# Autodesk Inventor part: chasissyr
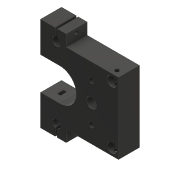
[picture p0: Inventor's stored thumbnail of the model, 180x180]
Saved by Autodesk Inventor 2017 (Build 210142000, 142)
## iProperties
Created: 2018-08
Part Number: chasissyr
Material: Plastic, Opaque Black
Document SubType Name: Modeling
Designer: JK
Density: 0.952 g/cm^3
Appearance: Smooth - Black
Author: JK
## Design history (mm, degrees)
sketch "Sketch1"
  geometry: L1 (15, 45)-(-15, 45); L2 (-15, 45)-(-15, -45); L3 (-15, -45)-(15, -45); L4 (15, -45)-(15, 45); L5 (15, 45)-(-15, -45); L6 (-15, 45)-(15, -45); L7 (-15, -45)-(-48.5, -45); L8 (-48.5, -45)-(-48.5, 45); L9 (-48.5, 45)-(-15, 45); L10 (-15, 45)-(-15, -45); C1 r 4.15 at (0, 34); C2 r 4.15 at (0, -34); 3 further points
  constraints: 20 end point, 4 parallel, 2 centre point, 2 horizontal, 2 midpoint, 2 perpendicular, 2 vertical alignment, 1 coincident, 1 equal radius
  dimensions: "d0" = 8.3 diameter of C1; "d4" = 68 distance of C2.centre C1.centre; "d5" = 34 distance of point (0, 0) C1.centre; "d6" = 90 distance of L3.end L1.start; "d7" = 30 distance of L1.start L1.end; "d14" = 33.5 distance of L8.end L9.end
extrude "Extrusion1" new body sketch "Sketch1" distance "d2" = 20; taper "d3" = 0 deg
sketch "Sketch2"
  geometry: L1 (-15, 45)-(-15, -45) reference; L2 (48.5, -45)-(48.5, 45) reference; L3 (3.5, -15.65)-(-15, -15.65); L4 (-15, 45)-(-15, -45) reference; L5 (-15, -15.65)-(-15, 15.65); L6 (-15, 15.65)-(3.5, 15.65); C1 r 4.15 at (0, 34) reference; C2 r 5 at (33.5, 0); A1 r 15.65 centre (3.5, 0) between (3.5, -15.65) and (3.5, 15.65); A2 r 15.65 centre (3.5, 0) between (3.5, 15.65) and (3.5, -15.65); 1 further point
  constraints: 6 end point, 4 point on circle, 3 centre point, 3 tangent, 2 point on line, 1 horizontal alignment, 1 perpendicular
  dimensions: "d9" = 31.3 diameter of A1; "d15" = 10 diameter of C2; "d16" = 15 distance from line of L2 C2.centre; "d67" = 30 distance of A1.centre C2.centre
extrude "Extrusion2" cut sketch "Sketch2" stored distance "d10" = 60.25; taper "d11" = 0 deg
sketch "Sketch3"
  geometry: L1 (63.5, 0)-(74.5, 0); L2 (74.5, 0)-(74.5, 20); L3 (74.5, 20)-(63.5, 20); L4 (63.5, 20)-(63.5, 0); L5 (63.5, 0)-(63.5, 20) reference; 1 further point
  constraints: 8 end point, 2 parallel, 1 collinear, 1 horizontal, 1 perpendicular
  dimensions: "d17" = 11 distance between parallel lines of L4 L2; "d18" = 20 distance of L1.end L2.end
extrude "Extrusion3" join sketch "Sketch3" stored distance "d19" = 86; taper "d20" = 0 deg
workplane "Work Plane1"
sketch "Sketch9"
  geometry: L1 (9.5, -53.432)-(66.206, -53.432); L2 (66.206, -53.432)-(66.206, -34); L3 (66.206, -34)-(9.5, -34); L4 (9.5, -34)-(9.5, -53.432); L5 (9.5, 53.45)-(78.426, 53.45); L6 (78.426, 53.45)-(78.426, 34); L7 (78.426, 34)-(9.5, 34); L8 (9.5, 34)-(9.5, 53.45); L9 (-15, -45)-(48.5, -45) reference; L10 (48.5, 45)-(-15, 45) reference; L11 (59.5, -45)-(59.5, 45) reference; 6 further points
  constraints: 16 end point, 4 parallel, 2 horizontal, 2 perpendicular, 1 point on line
  dimensions: "d48" = 11 distance between parallel lines of L3 L9; "d49" = 11 distance between parallel lines of L10 L7; "d50" = 50 distance between parallel lines of L11 L8
extrude "Extrusion9" cut sketch "Sketch9" stored distance "d51" = 44.25; taper "d52" = 0 deg
sketch "Sketch10"
  geometry: L1 (-1, -48.543)-(1, -48.543); L2 (1, -48.543)-(1, -31.463); L3 (1, -31.463)-(-1, -31.463); L4 (-1, -31.463)-(-1, -48.543); L5 (-1, 33.048)-(1, 33.048); L6 (1, 33.048)-(1, 46.501); L7 (1, 46.501)-(-1, 46.501); L8 (-1, 46.501)-(-1, 33.048); 1 further point
  constraints: 16 end point, 4 parallel, 2 horizontal, 2 perpendicular, 1 point on line
  dimensions: "d53" = 2 distance between parallel lines of L6 L8; "d54" = 2 distance of L1.start L1.end; "d55" = 1 distance from line of point (0, 0) L2
extrude "Extrusion10" cut sketch "Sketch10" distance "d56" = 44.25; taper "d57" = 0 deg
sketch "Sketch11"
  geometry: L1 (0, 0)-(0, 20) reference; L2 (-29.35, 0)-(0, 0) reference; L3 (-90, 0)-(-60.65, 0) reference; C1 r 1.85 at (-4, 10); C2 r 1.85 at (-86, 10); 1 further point
  constraints: 2 centre point, 1 equal radius
  dimensions: "d58" = 4 distance from line of L1 C1.centre; "d59" = 3.7 diameter of C1; "d60" = 4 horizontal distance of L3.start C2.centre; "d61" = 10 distance from line of L2 C1.centre; "d62" = 10 distance from line of L3 C2.centre
extrude "Extrusion11" cut sketch "Sketch11" distance "d63" = 44.25; taper "d64" = 0 deg
sketch "Sketch13"
  geometry: C1 r 1.85 at (22.5, 10); C2 r 1.85 at (67.5, 10); 1 further point
  constraints: 2 centre point
  dimensions: "d69" = 3.7 diameter of C1; "d70" = 3.7 diameter of C2; "d71" = 45 distance of C2.centre C1.centre; "d72" = 22.5 horizontal distance of point (45, 0) C1.centre
extrude "Extrusion13" cut sketch "Sketch13" distance "d73" = 20; taper "d74" = 0 deg
sketch "Sketch15"
  geometry: L1 (9, -7.2)-(12, -7.2); L2 (12, -7.2)-(12, -13); L3 (12, -13)-(9, -13); L4 (9, -13)-(9, -7.2); L5 (0, 0)-(14, 0) reference; L6 (0, -20)-(0, 0) reference; 1 further point
  constraints: 8 end point, 2 parallel, 1 horizontal, 1 perpendicular
  dimensions: "d75" = 3 distance of L1.start L1.end; "d76" = 5.8 distance of L3.end L1.start; "d77" = 7.2 distance between parallel lines of L5 L1; "d78" = 9 distance between parallel lines of L6 L4
extrude "Extrusion14" cut sketch "Sketch15" distance "d79" = 11.75; taper "d80" = 0 deg
mirror "Mirror3"
sketch "Sketch17"
  geometry: L1 (59.5, 34)-(59.5, -34) reference; L2 (59.5, 34)-(9.5, 34) reference; L3 (9.5, -34)-(59.5, -34) reference; C1 r 4.8 at (53, 27.5); C2 r 4.8 at (53, -27.5); 1 further point
  constraints: 2 centre point, 1 equal radius
  dimensions: "d81" = 9.6 diameter of C1; "d82" = 6.5 distance from line of L1 C1.centre; "d83" = 6.5 distance from line of L2 C1.centre; "d84" = 6.5 distance from line of L1 C2.centre; "d85" = 6.5 distance from line of L3 C2.centre
extrude "Extrusion15" cut sketch "Sketch17" distance "d86" = 10; taper "d87" = 0 deg
sketch "Sketch18"
  geometry: L1 (50, 20)-(50, 0) reference; L2 (50, 0)-(0, 0) reference; C1 r 1.85 at (43.5, 5); 1 further point
  constraints: 1 centre point
  dimensions: "d88" = 3.7 diameter of C1; "d89" = 6.5 distance from line of L1 C1.centre; "d90" = 5 distance from line of L2 C1.centre
extrude "Extrusion16" cut sketch "Sketch18" distance "d91" = 8.25; taper "d92" = 0 deg
sketch "Sketch19"
  geometry: C1 r 1.85 at (43.5, 5) reference; C2 r 1.4 at (43.5, 5); 1 further point
  constraints: 1 centre point, 1 coincident
  dimensions: "d93" = 2.8 diameter of C2
extrude "Extrusion17" cut sketch "Sketch19" distance "d94" = 14.25; taper "d95" = 0 deg
mirror "Mirror4"
sketch "Sketch20"
  geometry: C1 r 2.65 at (33.5, -18.25); C2 r 2.65 at (33.5, 18.25); C3 r 5 at (33.5, 0) reference; 1 further point
  constraints: 2 centre point, 2 vertical alignment, 1 equal radius
  dimensions: "d96" = 5.3 diameter of C1; "d97" = 18.25 distance of C3.centre C1.centre; "d98" = 36.5 distance of C2.centre C1.centre
extrude "Extrusion18" cut sketch "Sketch20" distance "d99" = 93; taper "d100" = 0 deg
body "Solid1"
